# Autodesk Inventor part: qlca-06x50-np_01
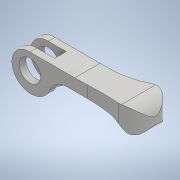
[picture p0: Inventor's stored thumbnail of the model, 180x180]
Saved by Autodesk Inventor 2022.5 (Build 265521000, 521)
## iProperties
Part Number: qlca-06x50-np_01
Material: 一般
Document SubType Name: Modeling
Designer: ImaoCorp
Density: 1 g/cm^3
Appearance: 既定
Author: ImaoCorp
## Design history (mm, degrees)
feature "qlca-06x50-np_01"
node "ソリッド1"
